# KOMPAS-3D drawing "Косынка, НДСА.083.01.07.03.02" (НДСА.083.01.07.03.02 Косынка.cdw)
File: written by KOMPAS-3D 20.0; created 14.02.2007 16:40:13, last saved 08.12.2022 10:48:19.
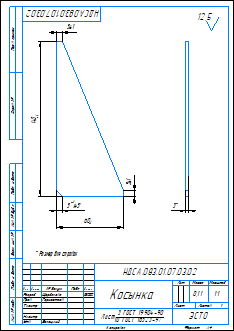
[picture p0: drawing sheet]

Sheet 1: A4, portrait

Document properties: Автор: Шубников; Организация: ЭСТО-Вакуум; Масса: 0.11018; Параметр неуказанной шероховатости: 12,5; PLM_CDWXDTO: <item xmlns="http://appius.ru/pdm" xmlns:xs="http://www.w3.org/2001/XMLSchema" xmlns:xsi="http://www.w3.org/2001/XMLSchema-instance" xsi:type="item">  <element xmlns:d2p1="http://v8.1c.ru/8.1/data/enterprise/current-config" xsi:type="d2p1:CatalogRef.aps_Элемен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; Полное имя файла: C:\Users\cherbakova\Desktop\Виноград\Новая папка (3)\НДСА.083.01.07.03.02 Косынка.cdw

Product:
- Part/product: Косынка  | designation НДСА.083.01.07.03.02
    Материал: Лист$d3 ГОСТ 19904-90;10 ГОСТ 16523-97$ (density 7856 kg/m3)
    Масса: 0.11018

Title block, sheet 1: Наименование: Косынка; designation: НДСА.083.01.07.03.02; Материал: Лист 3 ГОСТ 19904-90 10 ГОСТ 16523-97; Масса: 0,11; scale: 1:1; Количество листов документа: 1; organisation: ЭСТО; Форматы листов документа: A4; stored path: E:\WorkPDM\Шубников А.В\6175ff0c-3085-4b54-8dc5-0ee763079a8d\УКРД.787.01.12.10.02 Косынка.cdw; Разработал: Щербакова; Проверил: Горностаев; Утвердил: Белецкий; Разработал, date: 08.12.2022
Table, sheet 1:
  0;Material:VDE12371B5FDD453AAD3A0896F0FE5778;Sortament:VBE6DDF6ADAD111D69930000021274E8E^SortamentEx:V409D97DD20334DB28E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

Views: Вид 1, Спереди, Проекционный вид 2
Referenced files in C:\Users\cherbakova\Desktop\Виноград\Новая папка (3)\: НДСА.083.01.07.03.02 Косынка.m3d
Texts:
  НДСА.083.01.07.03.02 Косынка
Dimensions and other numbers on the sheet: 140; 60; 5±1; 3; 12,5; 1:1; 1; 0,11; 08.12.2022

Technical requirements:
  * Размер для справок.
